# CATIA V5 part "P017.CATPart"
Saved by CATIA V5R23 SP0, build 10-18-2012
Part number: P017
Definition: Rlt rigide d25 D47 b12
Description: Rlt rigide 6005 d25 D47 b12
Bounding box of the stored display mesh (mm): x -6 to 6, y -23.5 to 23.5, z -23.457 to 23.457
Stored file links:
  C:\wamp\www\COURS\CONCEPTION GMP1\TITRE 02-SEMESTRE 2\03-TP7-PRESSE MECANIQUE\eleve\P017.CATPart
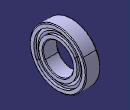
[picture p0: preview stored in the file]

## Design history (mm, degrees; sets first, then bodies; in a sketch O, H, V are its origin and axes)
Parameters
  PartNumber = "Rlt rigide 6005 d25 D47 b12"
  Designation = "Rlt_rigide_61804_d20_D32_b7"
  diametre_interieur = 25 mm
  diametre_exterieur = 47 mm
  largeur = 12 mm
  rayon = 0.6 mm
  diametre_bille = 9 mm
  diam_eplt_int = 32 mm
  diam_eplt_ext = 40.3 mm
  c_dynam = 11200 (force)
  co = 5600 (force)
Body1 (main body)
  Sketch1 on xy-plane, origin (0, 0, 0), H (1, 0, 0), V (0, 1, 0)
    axis line L1 (-6, 0) -> (6, 0)
    point P1 (-6, 0)
    point P2 (6, 0)
    arc A1 centre (0, 18) radius 4.5 from (-4.0311, 16) to (4.0311, 16) ccw
    point P3 (0, 18)
    line L2 (-6, 16) -> (-4.0311, 16)
    line L3 (6, 16) -> (6, 13.1)
    line L4 (5.4, 12.5) -> (-5.4, 12.5)
    line L5 (-6, 13.1) -> (-6, 16)
    point P6 (4.0311, 16)
    line L6 (4.0311, 16) -> (6, 16)
    arc A2 centre (5.4, 13.1) radius 0.6 from (6, 13.1) to (5.4, 12.5) cw
    arc A3 centre (-5.4, 13.1) radius 0.6 from (-5.4, 12.5) to (-6, 13.1) cw
    radius A2 = 0.6 {= rayon}
    radius A3 = 0.6 {= rayon}
    radius A1 = 4.5 {= diametre_bille /2}
    distance L4 L1 = 12.5 {= diametre_interieur /2}
    distance L5 L3 = 12 {= largeur}
    distance P3 L1 = 18 {= (diametre_exterieur+diametre_interieur )/4}
    distance L6 L1 = 16 {= diam_eplt_int /2}
    coincidence: P1 H, P3 V, L2 P6, L2 L6, P1 L5, P2 L3
    horizontal: L1 H, L2 H, L4 H, L6 H
    vertical: L3 V, L5 V
    symmetry: L3 L5 V
    tangency: A2 L3, A2 L4, A3 L4, A3 L5
  Shaft1: profile Sketch1, axis Sketch1.L1, angle 360
Body2
  Sketch2 on xy-plane, origin (0, 0, 0), H (1, 0, 0), V (0, 1, 0)
    circle A1 centre (0, 18) radius 4.5
    point P1 (0, 18)
    reference projected arc E1 centre (0, 18) radius 4.5 from (-4.0311, 16) to (4.0311, 16) ccw from element of Sketch1
    axis line L1 (-4.5, 0) -> (4.5, 0)
    point P2 (-4.5, 0)
    point P3 (4.5, 0)
    length L1 = 9 {= diametre_bille}
    coincidence: P1 V, A1 E1, P2 H
    horizontal: L1 H
    symmetry: P2 P3 V
  Shaft2: profile Sketch2, axis Sketch2.L1, angle 360
Body3
  Sketch3 on xy-plane, origin (0, 0, 0), H (1, 0, 0), V (0, 1, 0)
    line L1 (-5.4, 23.5) -> (5.4, 23.5)
    line L2 (6, 22.9) -> (6, 20.15)
    line L3 (6, 20.15) -> (3.9532, 20.15)
    line L4 (-6, 20.15) -> (-6, 22.9)
    reference projected line E1 (-6, 16) -> (-6, 13.1) from element of Sketch1
    reference projected line E2 (6, 13.1) -> (6, 16) from element of Sketch1
    arc A1 centre (0, 18) radius 4.5 from (3.9532, 20.15) to (-3.9532, 20.15) ccw
    point P3 (0, 18)
    reference projected arc E3 centre (0, 18) radius 4.5 from (-4.0311, 16) to (4.0311, 16) ccw from element of Sketch1
    arc A2 centre (-5.4, 22.9) radius 0.6 from (-5.4, 23.5) to (-6, 22.9) ccw
    arc A3 centre (5.4, 22.9) radius 0.6 from (6, 22.9) to (5.4, 23.5) ccw
    axis line L5 (-6, 0) -> (6, 0)
    point P10 (-6, 0)
    point P11 (6, 0)
    line L6 (-3.9532, 20.15) -> (-6, 20.15)
    radius A2 = 0.6 {= rayon}
    radius A3 = 0.6 {= rayon}
    distance L5 L1 = 23.5 {= diametre_exterieur /2}
    distance L3 P11 = 20.15 {= diam_eplt_ext /2}
    horizontal: L1 H, L3 H, L6 H
    vertical: L2 V, L4 V
    coincidence: E1 L4, L2 E2, P3 V, E3 A1, P10 L4, P11 L2, H L5, L3 L6
    tangency: A2 L1, A2 L4, A3 L2, A3 L1
  Shaft3: profile Sketch3, axis Sketch3.L5, angle 360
